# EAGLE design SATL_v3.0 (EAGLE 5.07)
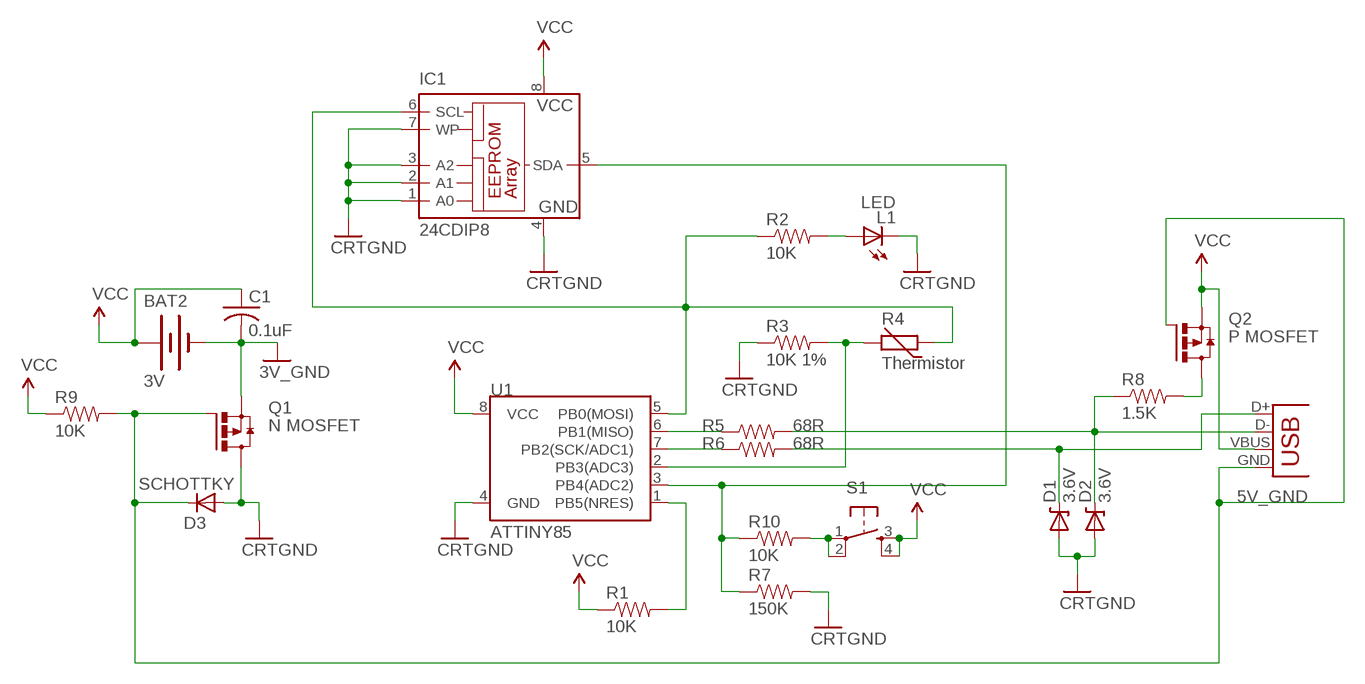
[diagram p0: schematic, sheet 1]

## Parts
BAT2  3V  BATTERYCR2302  [BATT_CR2032]
C1  0.1uF  C-US025-024X044  [C025-024X044]
D1  3.6V  DIODE-ZENERDIODEZENER5MM  [DIODE5MM]
D2  3.6V  DIODE-ZENERDIODEZENER5MM  [DIODE5MM]
D3  SCHOTTKY  DIODE5MM  [DIODE5MM]
IC1  24CDIP8  [DIP8]
L1  LED  LED3MM  [LED3MM]
Q1  N MOSFET  FDN360PNCHANNEL  [SUPER-SOT3]
Q2  P MOSFET  FDN360P  [SUPER-SOT3]
R1  10K  RESISTOR5MM  [RESISTOR5MM]
R2  10K  RESISTOR5MM  [RESISTOR5MM]
R3  10K 1%  RESISTOR5MM  [RESISTOR5MM]
R4  Thermistor  THERMISTOR-2,5  [RS-2,5]
R5  68R  RESISTOR5MM  [RESISTOR5MM]
R6  68R  RESISTOR5MM  [RESISTOR5MM]
R7  150K  RESISTOR5MM  [RESISTOR5MM]
R8  1.5K  RESISTOR5MM  [RESISTOR5MM]
R9  10K  RESISTOR5MM  [RESISTOR5MM]
R10  10K  RESISTOR5MM  [RESISTOR5MM]
S1  TAC_SWITCHPTH  [TACTILE-PTH]
U1  ATTINY85  ATTINY45DIP8  [DIP08]
X1  USBPTH  [USB-B-PTH]

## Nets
5V_GND: D3.P$1(C) Q1.1(G) Q2.1(G) R9.P$2 X1.GND
AIN0: IC1.6(SCL) R2.P$1 R4.1 U1.5(PB0(MOSI))
CRTGND: D1.P$2(A) D2.P$2(A) D3.P$2(A) IC1.1(A0) IC1.2(A1) IC1.3(A2) IC1.4(GND) IC1.7(WP) L1.K(C) Q1.2(D) R3.P$1 R7.P$2 U1.4(GND)
D+: D1.P$1(C) R6.P$2 X1.D+
D-: D2.P$1(C) R5.P$2 R8.P$1 X1.D-
GND: BAT2.2(-) C1.2 Q1.3(S) ; supply symbol labelled 3V_GND
N$1: R1.P$2 U1.1(PB5(NRES))
N$4: R5.P$1 U1.6(PB1(MISO))
N$6: R6.P$1 U1.7(PB2(SCK/ADC1))
N$9: L1.A R2.P$2
N$12: IC1.5(SDA) R7.P$1 R10.P$1 U1.3(PB4(ADC2))
N$19: Q2.3(D) R8.P$2
N$20: R3.P$2 R4.2 U1.2(PB3(ADC3))
N$23: R10.P$2 S1.1 S1.2
VCC: BAT2.1(+) C1.1 IC1.8(VCC) Q2.2(S) R1.P$1 R9.P$1 S1.3 S1.4 U1.8(VCC) X1.VBUS

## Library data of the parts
BAT2 = SparkFun:BATTERY: Battery Holders
C1 = adafruit:C-US: CAPACITOR, American symbol
D1 D2 = SparkFun:DIODE-ZENER: Zener Diode
D3 = SparkFun:DIODE: Diode
IC1 = microchip:24C*: Serial EEPROM 1 K/2 K/4 K
L1 = SparkFun:LED: LEDs
Q1 Q2 = transistor-power:FDN360P: Single P-Channel, PowerTrench (R) MOSFET Source: http://www.fairchildsemi.com/ds/FD/FDN360P.pdf
R1-R3 R5-R10 = SparkFun:RESISTOR: Resistor
R4 = varistor:THERMISTOR: THERMISTOR
S1 = SparkFun:TAC_SWITCH: Momentary Switch Button commonly used for reset or general input. Spark Fun Electronics SKU : COM-00097
U1 = SparkFun:ATTINY45: Atmel ATTiny45
X1 = SparkFun:USB: USB Connectors USB-B-PTH is fully proven SKU : PRT-00139 USB-miniB is fully proven SKU : PRT-00587 USB-A-PCB is untested. USB-A-H is throughly reviewed, but untested. Spark Fun Electronics SKU : PRT-00437 USB-B-SMT is throughly reviewed, but untested. Needs silkscreen touching up. USB-A-S has not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

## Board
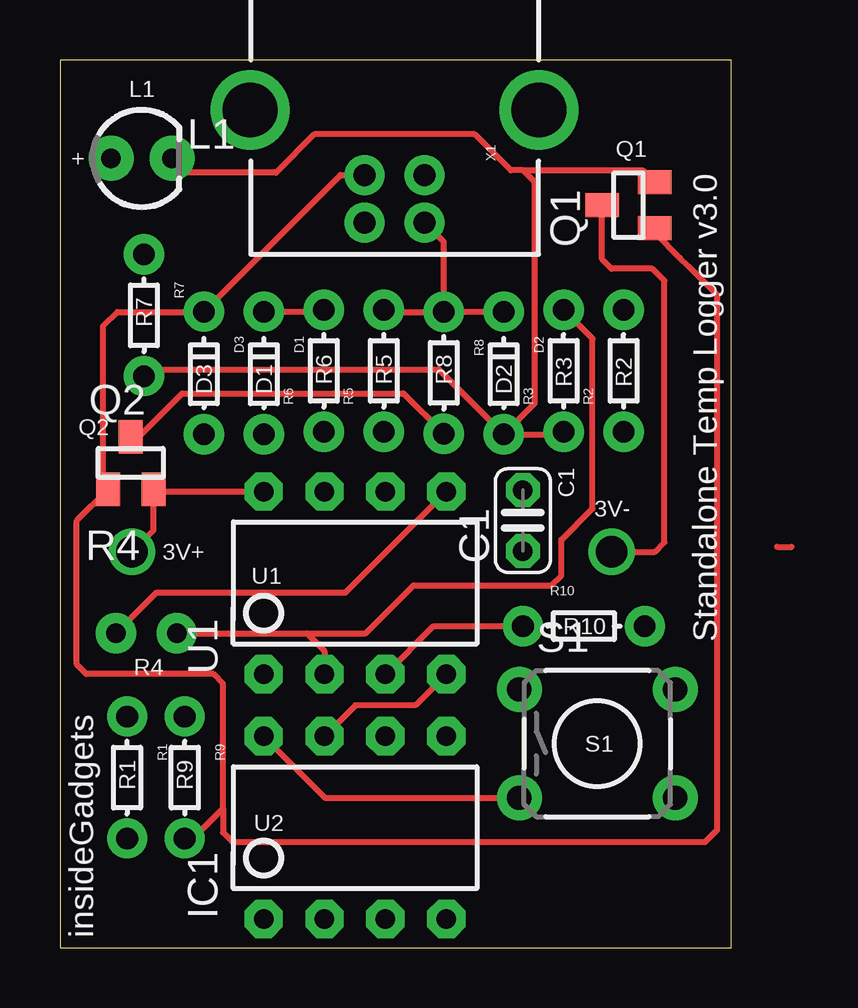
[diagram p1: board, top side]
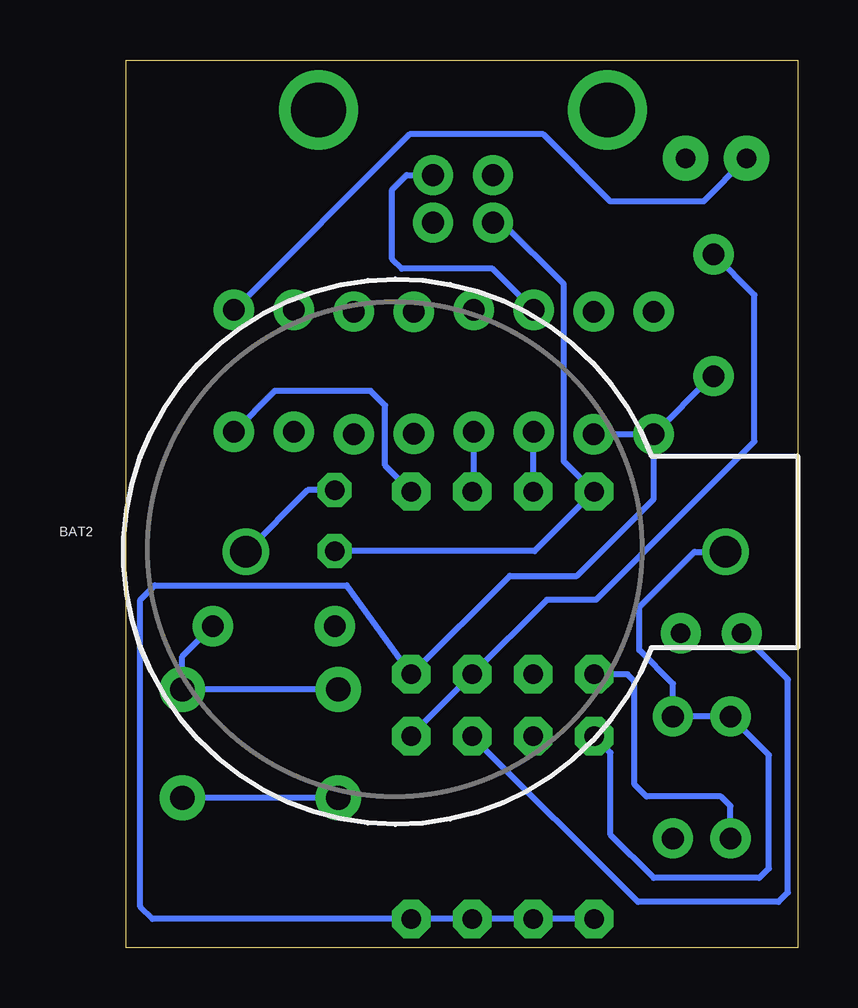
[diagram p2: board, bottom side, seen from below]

Size 28 x 37 mm. Coordinates in mm from the lower left corner, seen from the top.
Outline: 28,37 0,37 0,0 28,0 28,37
Copper layers (1*16): Top 0.035mm / dielectric 1.5mm / Bottom 0.035mm
Design rules "Fusion_eagle_rule_v1.1": minimum track width 6mil, minimum drill 12mil, track to track 6mil, track to pad 6mil, pad to pad 6mil, via to via 6mil, smd to smd 0mil, copper to edge 10mil, drill to drill 10mil, minimum pad ring 10mil, minimum via ring 6mil, stop-mask expansion 2mil, vias tented up to drill 100mil, thermal gap 10mil

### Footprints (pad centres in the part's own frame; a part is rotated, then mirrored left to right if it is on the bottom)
BATT_CR2032 = drill 1.3 round: 1 10.8,-0.4; 2 -9.2,-0.4
C025-024X044 = drill 0.813 pad 1.422 octagon: 1 -1.27,0; 2 1.27,0
DIODE5MM = drill 0.9 pad 1.676 round: P$1 -2.506,0; P$2 2.606,0
DIP8 = drill 0.813 pad 1.6 octagon: 1 -3.81,-3.81; 2 -1.27,-3.81; 3 1.27,-3.81; 4 3.81,-3.81; 5 3.81,3.81; 6 1.27,3.81; 7 -1.27,3.81; 8 -3.81,3.81
LED3MM = drill 0.813 pad 1.88 round: A -1.27,0; K 1.27,0
SUPER-SOT3 = smd 1 x 1.4: 1 -0.95,-1.1; 2 0.95,-1.1; 3 0,1.1
RESISTOR5MM = drill 0.9 pad 1.676 round: P$1 -2.5,0; P$2 2.58,0
RS-2,5 = drill 0.813 pad 1.676 round: 1 -1.27,0; 2 1.27,0
TACTILE-PTH = drill 1.016 pad 1.88 round: 1 -3.251,2.261; 2 3.251,2.261; 3 -3.251,-2.261; 4 3.251,-2.261
DIP08 = drill 0.813 pad 1.6 octagon: 1 -3.81,-3.81; 2 -1.27,-3.81; 3 1.27,-3.81; 4 3.81,-3.81; 5 3.81,3.81; 6 1.27,3.81; 7 -1.27,3.81; 8 -3.81,3.81
USB-B-PTH = drill 0.914 pad 1.676 round: D+ 0,1.25; D- 1.981,1.25; GND 0,-1.25; VBUS 1.981,-1.25 | drill 2.286 round: P$1 -2.718,-6.02; P$2 -2.718,6.02

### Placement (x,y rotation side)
BAT2  13.8,16.9 0 bottom
C1  19.3,17.8 90 top
D1  8.5,24 270 top
D2  18.5,24 270 top
D3  6,24 270 top
IC1  12.3,5 0 top
L1  3.4,32.9 0 top
Q1  23.7,30.95 90 top
Q2  2.95,20.2 0 top
R1  2.8,7.13 270 top
R2  23.5,24 90 top
R3  21,24 90 top
R4  3.6,13.1 0 top
R5  13.5,24 90 top
R6  11,24 90 top
R7  3.5,26.4 270 top
R8  16,24 270 top
R9  5.2,7.13 270 top
R10  21.8,13.4 0 top
S1  22.4,8.5 0 top
U1  12.3,15.2 0 top
X1  13.95,32.2 270 top

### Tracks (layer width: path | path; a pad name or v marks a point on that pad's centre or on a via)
5V_GND
  Top 0.254: Q1.1 24.8,29.8 25.85,28.75 26.2,28.4 27.4,27.2 27.4,4.9 26.9,4.4 7.2,4.4 6.8,4.8 6.8,5.8 | X1.GND 11.69,32.2 D3.P$1 2.4,26.5 1.8,25.9 1.8,19.3 Q2.1 0.7,17.8 0.7,11.8 1.1,11.4 6.4,11.4 6.8,11 6.8,5.8 | R9.P$2 5.55,4.55 6.8,5.8
AIN0
  Top 0.254: R4.1 4.03,14.8 11.9,14.8 U1.5
  Bottom 0.254: R2.P$1 21.8,23.2 17.8,23.2 17.2,22.6 17.2,20.1 U1.5 | IC1.6 6.66,1.9 0.8,1.9 0.4,2.3 0.4,11.17 R4.1
CRTGND
  Top 0.254: R3.P$1 20.89,21.39 D2.P$2 | D2.P$2 15.79,24.1 3.78,24.1 R7.P$2 | L1.K 5.27,32.3 9,32.3 10.6,33.9 17.3,33.9 18.8,32.4 19.3,32.4 | 19.3,32.4 24.3,32.4 Q1.2 | D2.P$2 19.8,22.69 19.8,31.9 19.3,32.4 | IC1.7 12.32,10.1 14.82,10.1 U1.4
  Bottom 0.254: R7.P$2 3.57,23.82 D3.P$2 | D3.P$2 D1.P$2 | D3.P$2 6,18.7 9.2,15.5 12,15.5 U1.4 18.8,15.1 26.8,15.1 27.4,14.5 27.4,1.7 26.89,1.19 IC1.4 IC1.3 IC1.2 IC1.1
D+
  Top 0.254: D1.P$1 10.96,26.51 R6.P$2
  Bottom 0.254: R6.P$2 12.72,28.3 16.5,28.3 16.9,28.7 16.9,31.6 16.3,32.2 X1.D+
D-
  Top 0.254: R5.P$2 13.58,26.5 R8.P$1 | R8.P$1 D2.P$1 | R8.P$1 16.01,29.41 X1.D-
GND
  Top 0.254: Q1.3 22.6,28.7 23,28.3 24.7,28.3 25.2,27.8 25.2,16.9 24.8,16.5 BAT2.2
  Bottom 0.254: C1.2 20.43,19.07 BAT2.2
N$1
  Bottom 0.254: U1.1 7.09,11.39 6.8,11.1 6.8,6.8 6.3,6.3 3.2,6.3 2.8,5.9 R1.P$2
N$4
  Bottom 0.254: R5.P$1 13.5,19.08 U1.6
N$6
  Bottom 0.254: U1.7 R6.P$1
N$9
  Bottom 0.254: R2.P$2 16.18,33.9 10.6,33.9 7.8,31.1 3.93,31.1 L1.A
N$11
  Top 0.254: 29.9,16.7 30.5,16.7
N$12
  Top 0.254: R10.P$1 15.58,13.4 U1.3
  Bottom 0.254: R7.P$1 1.8,27.2 1.8,21.1 8.4,14.5 10.46,14.5 U1.3 16.11,8.85 IC1.5
N$19
  Top 0.254: Q2.3 3.3,21.3 5.1,23.1 14.32,23.1 R8.P$2
N$20
  Top 0.254: R3.P$2 22.2,25.38 22.2,18.3 20.9,17 20.9,15.5 20.5,15.1 14.74,15.1 12.74,13.1 10.3,13.1 | R4.2 10.3,13.1 | U1.2 11.03,12.37 10.3,13.1
N$23
  Bottom 0.254: S1.1 S1.2 25.65,12.13 R10.P$2
VCC
  Top 0.254: U1.8 3.99,19.01 Q2.2 3.9,17.4 BAT2.1 | S1.3 11.06,6.24 IC1.8
  Bottom 0.254: C1.1 10.97,16.53 U1.8 9.75,20.27 9.75,27.65 12.32,30.22 X1.VBUS | S1.3 S1.4 | IC1.8 7.8,8.12 7.8,4.7 6,2.9 1.6,2.9 1.2,3.3 1.2,8.03 R1.P$1 R9.P$1 5.2,11 6.6,12.4 6.6,14.2 4.3,16.5 BAT2.1

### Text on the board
tPlace: L1 | + | Q1 | R7 | R6 | R5 | R8 | R3 | R2 | D3 | D1 | D2 | Q2 | C1 | 3V- | 3V+ | U1 | R10 | Standalone Temp Logger v3.0 | R4 | S1 | R1 | R9 | U2 | insideGadgets
bValues: USB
